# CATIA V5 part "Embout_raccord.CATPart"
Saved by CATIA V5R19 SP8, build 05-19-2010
Part number: Embout_raccord
Revision: ANY
Definition: UNKNOWN
Nomenclature: 4
Source: Unknown
Bounding box of the stored display mesh (mm): x -13.5 to 0, y -15.9 to 20.1, z -23.6 to 0
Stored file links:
  D:\Documents\1_Travail\2- 2I2D\1 - Cours et TD\2- TD\3-TD Assemblage\Pompe AirMan_Corrigé\Embout_raccord.CATPart
  D:\Documents\1_Travail\2- 2I2D\1 - Cours et TD\2- TD\3-TD Assemblage\Pompe AirMan\0-PompeAirman.CATProduct
  D:\Documents\1_Travail\2- 2I2D\1 - Cours et TD\2- TD\3-TD Assemblage\Pompe AirMan\Embout_corps_cylindre.CATPart
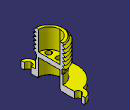
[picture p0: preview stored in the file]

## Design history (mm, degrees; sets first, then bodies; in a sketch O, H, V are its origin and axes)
Set1
  DatumCurve1
Body1 "Enlèvement de matière-Révolution1" (main body)
  Solid1: solid without history
  Sketch1 on face of Solid1, origin (0, 0, -20), H (1, 0, 0), V (0, 1, 0)
    arc A1 centre (0, -11.9) radius 2 from (0, -9.9) to (0, -13.9) ccw
    line L1 (0, -9.9) -> (0, -13.9)
    point P2 (0, -9.9)
    reference projected point E1 (-2, -11.9) from vertex [face of Solid1 | face of Solid1 | face of Solid1]
    reference projected arc E2 centre (0, -11.9) radius 2 from (0, -9.9) to (-2, -11.9) ccw from edge [face of Solid1 | face of Solid1]
    coincidence: P2 V, A1 E1, A1 E2
    vertical: L1 V
  Pad1: profile Sketch1, direction (0, 0, 1), up to face of Solid1
  Sketch2 on face of Solid1, origin (0, 0, -20), H (1, 0, 0), V (0, 1, 0)
    circle A1 centre (0, -12) radius 2
    reference projected arc E1 centre (0, -12) radius 2 from (0, -10) to (-2, -12) ccw from edge of DatumCurve1
    coincidence: A1 E1
  Pocket1: profile Sketch2, direction (0, 0, -1), through (limit type 3)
